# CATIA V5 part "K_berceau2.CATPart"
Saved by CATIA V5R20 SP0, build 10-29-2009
Part number: berceau2
Publications: "Arête"
Bounding box of the stored display mesh (mm): x -20 to 20, y -5 to 5, z -10 to 62
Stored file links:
  G:\Khaled_CFAO_2011\SIL\SIL_GR2\mdupuis\Khaled\CAD_ThinkMOTION\K_berceau2.CATPart
  G:\Dupuis_Maxime_Thinkmotion_CFAO\assemblage.CATProduct
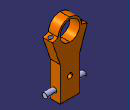
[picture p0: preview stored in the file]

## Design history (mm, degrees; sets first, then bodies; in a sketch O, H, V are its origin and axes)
External parameters (linked from other documents)
  External.diametrelunette = 20 mm
Set1
  Line1: linked copy from another document
  Point1: linked copy from another document
  Line2: linked copy from another document
  Point2: linked copy from another document
Body1 (main body)
  Sketch1 on zx-plane, origin (0, 0, 0), H (-1, 0, 0), V (0, 0, 1)
    point P1 (10, -10)
    line L1 (10, -10) -> (10, 25)
    point P2 (10, 25)
    line L2 (10, 25) -> (17.7841, 48.0463)
    point P3 (17.7841, 48.0463)
    point P4 (0, 50)
    reference projected point E1 (0, 50) from Point1
    line L3 (10, -10) -> (0, -10)
    point P5 (0, -10)
    reference projected line E2 (20, 0) -> (0, 0) from Line1
    circle A1 centre (0, 10) radius 2.5
    point P6 (0, 10)
    point P7 (0, 12.5)
    reference projected point E3 (0, 0) from Point2
    arc A2 centre (0, 50) radius 10 from (0, 40) to (0, 60) ccw
    point P8 (0, 60)
    point P9 (0, 40)
    arc A3 centre (0, 50) radius 12 from (12, 50) to (0, 62) ccw
    point P10 (0, 62)
    point P11 (12, 50)
    line L4 (17.7841, 48.0463) -> (12, 50)
    point P12 (0, -10)
    point P13 (-10, -10)
    line L5 (-10, -10) -> (0, -10)
    point P14 (-10, 25)
    line L6 (-10, -10) -> (-10, 25)
    point P15 (-17.7841, 48.0463)
    line L7 (-10, 25) -> (-17.7841, 48.0463)
    point P16 (-12, 50)
    line L8 (-17.7841, 48.0463) -> (-12, 50)
    point P17 (0, 62)
    arc A4 centre (0, 50) radius 12 from (-12, 50) to (0, 62) cw
    point P19 (0, 60)
    point P20 (0, 40)
    arc A5 centre (0, 50) radius 10 from (0, 40) to (0, 60) cw
    length L1 = 35
    length L3 = 10
    distance L3 E2 = 10
    radius A1 = 2.5
    distance P6 E3 = 10
    radius A2 = 10 {= External.diametrelunette /2}
    radius A3 = 12 {= External.diametrelunette /2 +2mm}
    vertical: L1 V
    coincidence: P4 V, P4 E1, P5 V, P6 V, A1 P7, P7 V, P8 V, P9 V, P10 V
    horizontal: L3 H
    perpendicularity: L4 L2
    symmetry: P5 P12 V, P1 P13 V, L3 L5 V, P2 P14 V, L1 L6 V, P3 P15 V, L2 L7 V, P11 P16 V, L4 L8 V, P10 P17 V, A3 A4 V, P8 P19 V, P9 P20 V, A2 A5 V
  Pad1: profile Sketch1, direction (0, 1, 0), length 5, mirrored extent
  Sketch2 on face of Pad1 from Sketch1.L4, origin (-15.6236, 2.3799, 48.7761), H (0.9474, 0, 0.32), V (0, 1, 0)
    point P1 (0.772, -2.3799)
    reference projected line E1 (-2.2805, -2.3799) -> (3.8247, -2.3799) from Sketch1.L4
    distance P1 E1 = 0
  Hole1: placed by Sketch2, at (-14.8921, 0, 49.0231) direction (0.32, 0, -0.9474), diameter 4, depth 20
  Mirror1: of Hole1, about yz-plane
  Sketch3 on yz-plane, origin (0, -0.8605, -0.3916), H (0, 1, 0), V (0, 0, 1)
    point P1 (0, 0)
  Hole2: placed by Sketch3, at (0, -0.8605, -0.3916) direction (-1, 0, 0), diameter 5, depth 10.5
  Sketch4 on yz-plane, origin (0, 0, 0), H (0, 1, 0), V (0, 0, 1)
    circle A1 centre (-0.8605, -0.3916) radius 2.5
    point P1 (-0.8605, -0.3916)
    reference projected point E1 (-0.8605, -0.3916) from Sketch3
    reference projected circle E2 centre (-0.8605, -0.3916) radius 2.5 from edge [face of Hole2 | face of Pad1 from Sketch1.L6]
    distance P1 E1 = 0
    tangency: A1 E2
  Pad2: profile Sketch4, direction (1, 0, 0), length 20, mirrored extent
